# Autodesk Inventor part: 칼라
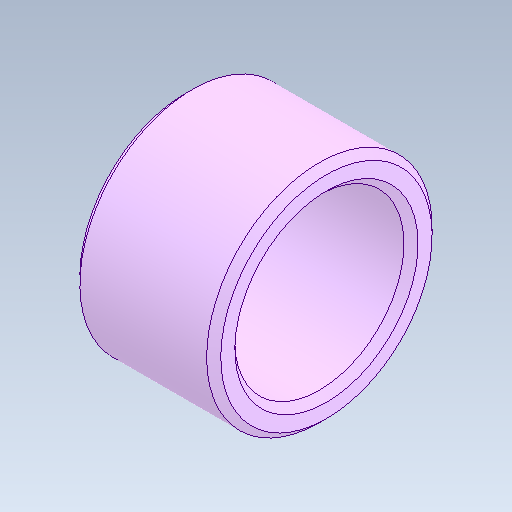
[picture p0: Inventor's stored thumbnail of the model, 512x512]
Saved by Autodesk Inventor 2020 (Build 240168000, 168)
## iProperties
Created: 2024-05
Part Number: 칼라
Material: 강철, 합금
Document SubType Name: Modeling
Designer: oem
Density: 7.73 g/cm^3
Appearance: 기본값
Author: jhkim
Sending System: Autodesk Inventor 2025
Preprocessor: ST-DEVELOPER v20
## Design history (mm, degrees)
feature "솔리드1"
node "솔리드2"
